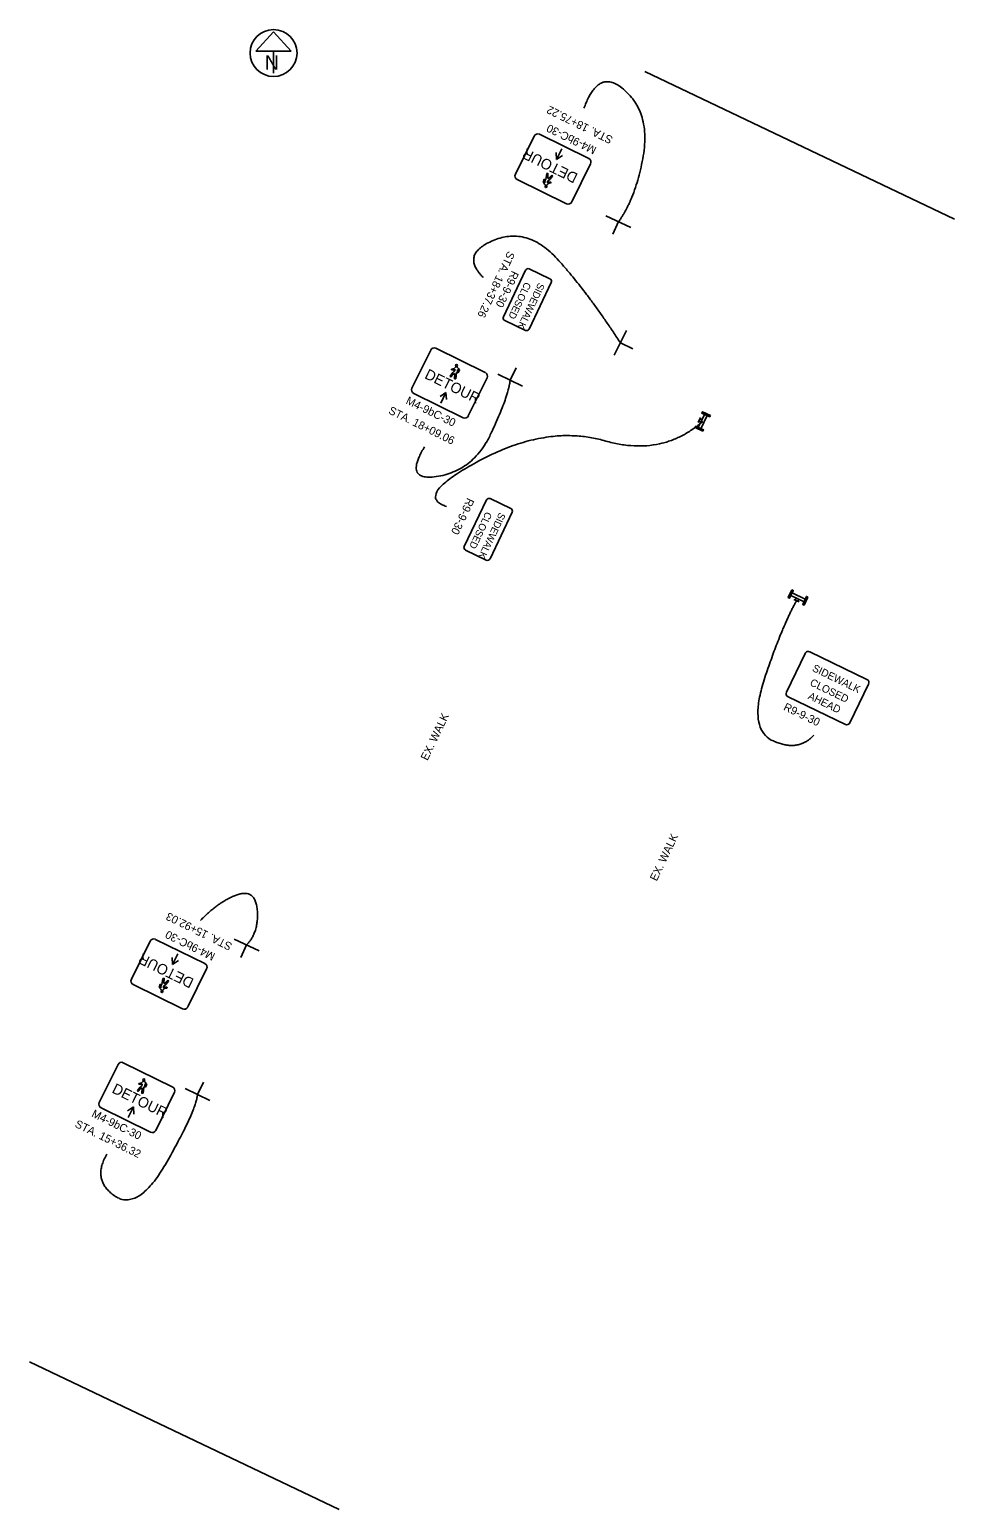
# Model space of a CAD drawing. Extents: x 185971 to 186295, y 352062 to 352579.
import ezdxf

# ---------------------------------------------------------------- set-up
doc = ezdxf.new("R2010")
doc.units = 0
for name, color, linetype in [('Default', 7, 'Continuous'), ('SH_Data', 7, 'Continuous'), ('SH_Masking', 7, 'Continuous')]:
    doc.layers.add(name, color=color, linetype=linetype)

msp = doc.modelspace()

# ---------------------------------------------------------------- linework, layer by layer
at = {"layer": 'SH_Data'}
for p, q in [((186294.98, 352513.13), (186186.66, 352564.77)), ((186079.8, 352061.8), (185971.48, 352113.45))]:
    msp.add_line(p, q, dxfattribs=at)
msp.add_circle((186056.82, 352571.28), 8.2, dxfattribs=at)
at = {"layer": 'SH_Masking'}
for p, q in [((186056.82, 352578.76), (186050.67, 352571.93)), ((186062.98, 352571.93), (186056.82, 352578.76)), ((186050.67, 352571.93), (186062.98, 352571.93)), ((186056.82, 352571.93), (186056.82, 352564.2)), ((186155.79, 352534), (186155.63, 352536.51)), ((186155.79, 352534), (186157.65, 352537.78)), ((186155.79, 352534), (186157.88, 352535.4)), ((186151.53, 352527.13), (186151.1, 352526.05)), ((186151.1, 352526.05), (186151.1, 352526.04)), ((186151.44, 352526.05), (186151.75, 352527)), ((186151.69, 352525.92), (186151.44, 352526.05)), ((186151.75, 352527), (186151.53, 352527.13)), ((186152.11, 352527.07), (186152.06, 352527.05)), ((186152.39, 352529.19), (186152.11, 352527.07)), ((186152.82, 352529.28), (186152.39, 352529.19)), ((186152.68, 352526.49), (186153.01, 352526.73)), ((186152.68, 352525.9), (186152.68, 352526.49)), ((186152.98, 352526.12), (186152.68, 352525.9)), ((186152.73, 352527.36), (186152.82, 352529.28)), ((186153.14, 352527.55), (186152.73, 352527.36)), ((186153.83, 352526.1), (186152.98, 352526.12)), ((186153.01, 352526.73), (186153.44, 352527.07)), ((186154.11, 352528.61), (186153.14, 352527.55)), ((186153.44, 352527.07), (186154.38, 352528.25)), ((186153.87, 352525.82), (186153.83, 352526.1)), ((186154.38, 352528.25), (186154.11, 352528.61)), ((186152.91, 352525.64), (186153.87, 352525.82)), ((186181.81, 352510.3), (186173.1, 352514.31)), ((186177.45, 352512.31), (186175.45, 352507.95)), ((186176.02, 352465.62), (186180.27, 352474.23)), ((186178.15, 352469.93), (186182.45, 352467.8)), ((186119.5, 352459.47), (186118.55, 352458.3)), ((186118.82, 352457.94), (186119.8, 352459)), ((186120.02, 352460.91), (186119.06, 352460.73)), ((186119.06, 352460.73), (186119.1, 352460.45)), ((186119.1, 352460.45), (186119.95, 352460.43)), ((186119.93, 352459.82), (186119.5, 352459.47)), ((186119.8, 352459), (186120.2, 352459.19)), ((186120.25, 352460.06), (186119.93, 352459.82)), ((186119.95, 352460.43), (186120.25, 352460.65)), ((186120.2, 352459.19), (186120.12, 352457.27)), ((186120.25, 352460.65), (186120.25, 352460.06)), ((186120.54, 352457.35), (186120.82, 352459.48)), ((186120.82, 352459.48), (186120.87, 352459.5)), ((186121.5, 352460.5), (186121.19, 352459.55)), ((186121.19, 352459.55), (186121.4, 352459.42)), ((186121.24, 352460.63), (186121.5, 352460.5)), ((186121.4, 352459.42), (186121.84, 352460.5)), ((186121.84, 352460.5), (186121.83, 352460.51)), ((186143.9, 352454.73), (186135.29, 352458.98)), ((186139.6, 352456.85), (186141.72, 352461.16)), ((186118.55, 352458.3), (186118.82, 352457.94)), ((186120.12, 352457.27), (186120.54, 352457.35)), ((186117.14, 352452.55), (186115.05, 352451.15)), ((186117.14, 352452.55), (186115.28, 352448.77)), ((186117.14, 352452.55), (186117.31, 352450.04)), ((186205.35, 352441.98), (186206.21, 352443.83)), ((186207.54, 352444.89), (186205.39, 352440.28)), ((186206.68, 352443.05), (186205.99, 352443.37)), ((186208.47, 352444.46), (186206.31, 352439.85)), ((186206.25, 352442.12), (186205.56, 352442.45)), ((186206.93, 352442.37), (186206.93, 352442.37)), ((186237.76, 352381.47), (186242.38, 352379.32)), ((186238.19, 352382.4), (186242.81, 352380.24)), ((186240.67, 352379.28), (186238.83, 352380.14)), ((186239.61, 352380.61), (186239.29, 352379.92)), ((186240.53, 352380.18), (186240.21, 352379.49)), ((186240.29, 352380.86), (186240.29, 352380.86)), ((186242.74, 352361.23), (186236.21, 352347.75)), ((186264.38, 352352.15), (186244.44, 352361.82)), ((186258.42, 352336.94), (186264.98, 352350.45)), ((186236.8, 352346.06), (186256.84, 352336.34)), ((186051.77, 352257.25), (186043.05, 352261.26)), ((186047.41, 352259.26), (186045.4, 352254.9)), ((186021.47, 352252.37), (186021.31, 352254.88)), ((186021.47, 352252.37), (186023.33, 352256.15)), ((186021.47, 352252.37), (186023.56, 352253.77)), ((186018.07, 352247.57), (186017.79, 352245.44)), ((186018.5, 352247.65), (186018.07, 352247.57)), ((186018.41, 352245.73), (186018.5, 352247.65)), ((186019.79, 352246.98), (186018.81, 352245.93)), ((186019.12, 352245.45), (186020.06, 352246.62)), ((186020.06, 352246.62), (186019.79, 352246.98)), ((186017.21, 352245.5), (186016.78, 352244.42)), ((186016.78, 352244.42), (186016.78, 352244.42)), ((186017.12, 352244.43), (186017.43, 352245.38)), ((186017.37, 352244.29), (186017.12, 352244.43)), ((186017.43, 352245.38), (186017.21, 352245.5)), ((186017.79, 352245.44), (186017.74, 352245.42)), ((186018.36, 352244.86), (186018.69, 352245.1)), ((186018.36, 352244.27), (186018.36, 352244.86)), ((186018.66, 352244.49), (186018.36, 352244.27)), ((186018.81, 352245.93), (186018.41, 352245.73)), ((186018.59, 352244.02), (186019.55, 352244.2)), ((186019.51, 352244.47), (186018.66, 352244.49)), ((186018.69, 352245.1), (186019.12, 352245.45)), ((186019.55, 352244.2), (186019.51, 352244.47)), ((186010.66, 352210.98), (186009.7, 352210.8)), ((186009.7, 352210.8), (186009.74, 352210.53)), ((186009.74, 352210.53), (186010.59, 352210.51)), ((186010.59, 352210.51), (186010.89, 352210.73)), ((186010.89, 352210.73), (186010.89, 352210.14)), ((186012.13, 352210.57), (186011.82, 352209.62)), ((186011.88, 352210.71), (186012.13, 352210.57)), ((186012.04, 352209.49), (186012.47, 352210.58)), ((186012.47, 352210.58), (186012.47, 352210.58)), ((186030.24, 352206.93), (186032.36, 352211.24)), ((186010.13, 352209.55), (186009.19, 352208.38)), ((186009.19, 352208.38), (186009.46, 352208.02)), ((186009.46, 352208.02), (186010.44, 352209.07)), ((186010.56, 352209.9), (186010.13, 352209.55)), ((186010.44, 352209.07), (186010.84, 352209.27)), ((186010.89, 352210.14), (186010.56, 352209.9)), ((186010.84, 352209.27), (186010.75, 352207.35)), ((186010.75, 352207.35), (186011.18, 352207.43)), ((186011.18, 352207.43), (186011.46, 352209.55)), ((186011.46, 352209.55), (186011.51, 352209.58)), ((186011.82, 352209.62), (186012.04, 352209.49)), ((186034.54, 352204.81), (186025.93, 352209.05)), ((186007.78, 352202.63), (186005.69, 352201.23)), ((186007.78, 352202.63), (186005.92, 352198.85)), ((186007.78, 352202.63), (186007.94, 352200.12))]:
    msp.add_line(p, q, dxfattribs=at)
for points in [[(186147.98, 352542.23), (186141.42, 352528.91)], [(186167.09, 352534.34), (186149.82, 352542.86)], [(186161.15, 352519.18), (186167.71, 352532.5)], [(186142.04, 352527.07), (186159.31, 352518.56)], [(186144.95, 352495.29), (186137.21, 352479.04)], [(186153.51, 352492.32), (186146.29, 352495.76)], [(186146.23, 352474.73), (186153.98, 352490.98)], [(186137.68, 352477.71), (186144.9, 352474.26)], [(186111.79, 352467.37), (186105.22, 352454.05)], [(186130.89, 352459.48), (186113.63, 352467.99)], [(186124.95, 352444.32), (186131.52, 352457.64)], [(186105.84, 352452.21), (186123.11, 352443.69)], [(186131.26, 352414.93), (186123.52, 352398.68)], [(186139.82, 352411.96), (186132.6, 352415.4)], [(186132.54, 352394.38), (186140.29, 352410.62)], [(186123.99, 352397.35), (186131.21, 352393.9)], [(186013.66, 352260.6), (186007.1, 352247.28)], [(186032.77, 352252.72), (186015.5, 352261.23)], [(186026.83, 352237.56), (186033.39, 352250.88)], [(186007.72, 352245.44), (186024.99, 352236.93)], [(186002.42, 352217.44), (185995.86, 352204.12)], [(186021.53, 352209.56), (186004.26, 352218.07)], [(186015.59, 352194.4), (186022.16, 352207.71)], [(185996.48, 352202.28), (186013.75, 352193.77)]]:
    msp.add_lwpolyline(points, dxfattribs=at)
for points in [[(186209.61, 352444.49), (186206.84, 352445.78), (186206.62, 352445.32), (186209.39, 352444.03)], [(186207.02, 352438.96), (186204.25, 352440.25), (186204.47, 352440.71), (186207.24, 352439.42)], [(186238.16, 352383.53), (186236.87, 352380.77), (186237.33, 352380.55), (186238.63, 352383.32)], [(186243.7, 352380.95), (186242.41, 352378.18), (186241.95, 352378.4), (186243.24, 352381.17)]]:
    msp.add_lwpolyline(points, close=True, dxfattribs=at)
for centre, radius in [((186056.82, 352571.28), 8.2), ((186152.12, 352524.56), 0.337), ((186120.81, 352461.98), 0.337), ((186017.8, 352242.94), 0.337), ((186011.45, 352212.06), 0.337)]:
    msp.add_circle(centre, radius, dxfattribs=at)
for centre, radius, start, end in [((186149.22, 352541.62), 1.38, 63.7561, 153.7561), ((186166.48, 352533.11), 1.38, 333.7561, 63.7561), ((186142.65, 352528.3), 1.38, 153.7561, 243.7561), ((186159.91, 352519.79), 1.38, 243.7561, 333.7561), ((186145.86, 352494.86), 1, 64.5098, 154.5098), ((186153.08, 352491.41), 1, 334.5098, 64.5098), ((186138.11, 352478.61), 1, 154.5098, 244.5098), ((186145.33, 352475.17), 1, 244.5098, 334.5098), ((186113.02, 352466.76), 1.38, 63.7561, 153.7561), ((186130.29, 352458.25), 1.38, 333.7561, 63.7561), ((186106.45, 352453.44), 1.38, 153.7561, 243.7561), ((186123.72, 352444.93), 1.38, 243.7561, 333.7561), ((186132.17, 352414.5), 1, 64.5098, 154.5098), ((186139.39, 352411.05), 1, 334.5098, 64.5098), ((186124.42, 352398.25), 1, 154.5098, 244.5098), ((186131.64, 352394.81), 1, 244.5098, 334.5098), ((186243.89, 352360.68), 1.27, 64.1425, 154.1425), ((186263.83, 352351.01), 1.27, 334.1425, 64.1425), ((186237.35, 352347.2), 1.27, 154.1425, 244.1425), ((186257.3, 352337.53), 1.27, 244.1425, 334.1425), ((186014.9, 352260), 1.38, 63.7561, 153.7561), ((186032.16, 352251.48), 1.38, 333.7561, 63.7561), ((186008.33, 352246.68), 1.38, 153.7561, 243.7561), ((186025.59, 352238.16), 1.38, 243.7561, 333.7561), ((186003.66, 352216.83), 1.38, 63.7561, 153.7561), ((186020.92, 352208.32), 1.38, 333.7561, 63.7561), ((185997.09, 352203.52), 1.38, 153.7561, 243.7561), ((186014.36, 352195), 1.38, 243.7561, 333.7561)]:
    msp.add_arc(centre, radius, start, end, dxfattribs=at)
for points, degree in [([(186165.39, 352551.94), (186170.55, 352566.49), (186188.64, 352550.17), (186183.74, 352521), (186177.51, 352512.28)], 2), ([(186151.1, 352526.04), (186151.35, 352525.76), (186151.72, 352525.29), (186151.86, 352525.13), (186151.91, 352525.08), (186151.97, 352525.06), (186152.11, 352524.99), (186152.37, 352525.07), (186152.6, 352525.28), (186152.78, 352525.43), (186152.91, 352525.64)], 3), ([(186152.06, 352527.05), (186152, 352527.01), (186151.92, 352526.94), (186151.85, 352526.76), (186151.8, 352526.6), (186151.75, 352526.31), (186151.72, 352526.11), (186151.69, 352525.92)], 3), ([(186130.18, 352492.77), (186122.01, 352500.87), (186145.31, 352510.56), (186165.4, 352489.36), (186178.15, 352469.93)], 2), ([(186121.83, 352460.51), (186121.59, 352460.79), (186121.21, 352461.25), (186121.07, 352461.42), (186121.02, 352461.46), (186120.96, 352461.49), (186120.82, 352461.56), (186120.56, 352461.48), (186120.34, 352461.27), (186120.16, 352461.11), (186120.02, 352460.91)], 3), ([(186120.87, 352459.5), (186120.94, 352459.54), (186121.01, 352459.61), (186121.09, 352459.79), (186121.13, 352459.95), (186121.18, 352460.24), (186121.22, 352460.44), (186121.24, 352460.63)], 3), ([(186109.63, 352433.53), (186102.01, 352421.12), (186126.79, 352425.31), (186138.86, 352450.83), (186139.6, 352456.85)], 2), ([(186117.29, 352412.66), (186105.66, 352416.44), (186152.87, 352441.39), (186192.49, 352429.88), (186206.93, 352442.37)], 2), ([(186245.76, 352332.63), (186240.31, 352326.63), (186222.73, 352334.74), (186234.41, 352370.11), (186239.75, 352379.71)], 2), ([(186031.25, 352267.87), (186038.46, 352275.14), (186050.65, 352278.78), (186051.63, 352263.62), (186047.41, 352259.26)], 2), ([(186016.78, 352244.42), (186017.03, 352244.13), (186017.4, 352243.67), (186017.54, 352243.5), (186017.59, 352243.46), (186017.65, 352243.43), (186017.79, 352243.36), (186018.05, 352243.44), (186018.28, 352243.66), (186018.45, 352243.81), (186018.59, 352244.02)], 3), ([(186017.74, 352245.42), (186017.68, 352245.38), (186017.6, 352245.31), (186017.53, 352245.13), (186017.48, 352244.97), (186017.43, 352244.68), (186017.4, 352244.48), (186017.37, 352244.29)], 3), ([(186012.47, 352210.58), (186012.23, 352210.87), (186011.85, 352211.33), (186011.71, 352211.5), (186011.66, 352211.54), (186011.6, 352211.57), (186011.46, 352211.64), (186011.2, 352211.56), (186010.98, 352211.34), (186010.8, 352211.19), (186010.66, 352210.98)], 3), ([(186011.51, 352209.58), (186011.57, 352209.62), (186011.65, 352209.69), (186011.72, 352209.87), (186011.77, 352210.03), (186011.82, 352210.32), (186011.86, 352210.52), (186011.88, 352210.71)], 3), ([(185998.56, 352186.09), (185993.12, 352177.12), (186009.47, 352165.78), (186029.5, 352200.91), (186030.24, 352206.93)], 2)]:
    msp.add_open_spline(points, degree=degree, dxfattribs=at)

# ---------------------------------------------------------------- texts
at = {"layer": 'Default'}
for p in [(186110.66, 352323.56), (186190.84, 352281.38)]:
    msp.add_text('EX. WALK', height=2.8, rotation=64.5098, dxfattribs=at).set_placement(p)
at = {"layer": 'SH_Masking'}
msp.add_text('N', height=5, dxfattribs=at).set_placement((186053.8, 352565.46))
for s, height, rotation, p in [('STA. 18+75.22', 2.8, 153.7561, (186175.77, 352541.87)), ('M4-9bC-30', 2.8, 153.7561, (186170.02, 352538.24)), ('DETOUR', 3.667, 153.7561, (186163.56, 352528.89)), ('STA. 18+37.26', 2.8, 244.5098, (186138.83, 352502.19)), ('R9-9-30', 2.8, 244.5098, (186140.22, 352495.34)), ('CLOSED', 2.5, 244.5098, (186144.78, 352491.37)), ('SIDEWALK', 2.5, 244.5098, (186149.51, 352491.12)), ('DETOUR', 3.667, 333.7561, (186109.37, 352457.66)), ('M4-9bC-30', 2.8, 333.7561, (186102.85, 352448.76)), ('STA. 18+09.06', 2.8, 333.7561, (186096.78, 352445.29)), ('R9-9-30', 2.8, 244.5098, (186124.63, 352415.89)), ('CLOSED', 2.5, 244.5098, (186131.09, 352411.01)), ('SIDEWALK', 2.5, 244.5098, (186135.82, 352410.76)), ('SIDEWALK', 2.627, 334.1425, (186245.02, 352355.21)), ('CLOSED', 2.627, 334.1425, (186244.2, 352350.19)), ('AHEAD', 2.627, 334.1425, (186243.53, 352345.48)), ('R9-9-30', 2.8, 334.1425, (186234.93, 352341.59)), ('STA. 15+92.03', 2.8, 153.7561, (186042.6, 352259.69)), ('M4-9bC-30', 2.8, 153.7561, (186036.66, 352256.15)), ('DETOUR', 3.667, 153.7561, (186029.24, 352247.26)), ('DETOUR', 3.667, 333.7561, (186000.01, 352207.74)), ('M4-9bC-30', 2.8, 333.7561, (185992.93, 352199.31)), ('STA. 15+36.32', 2.8, 333.7561, (185987.08, 352195.72))]:
    msp.add_text(s, height=height, rotation=rotation, dxfattribs=at).set_placement(p)

doc.saveas('drawing.dxf')
